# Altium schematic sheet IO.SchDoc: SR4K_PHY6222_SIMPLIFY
size A4; Revision: V1.2; SheetNumber: 5; SheetTotal: 5
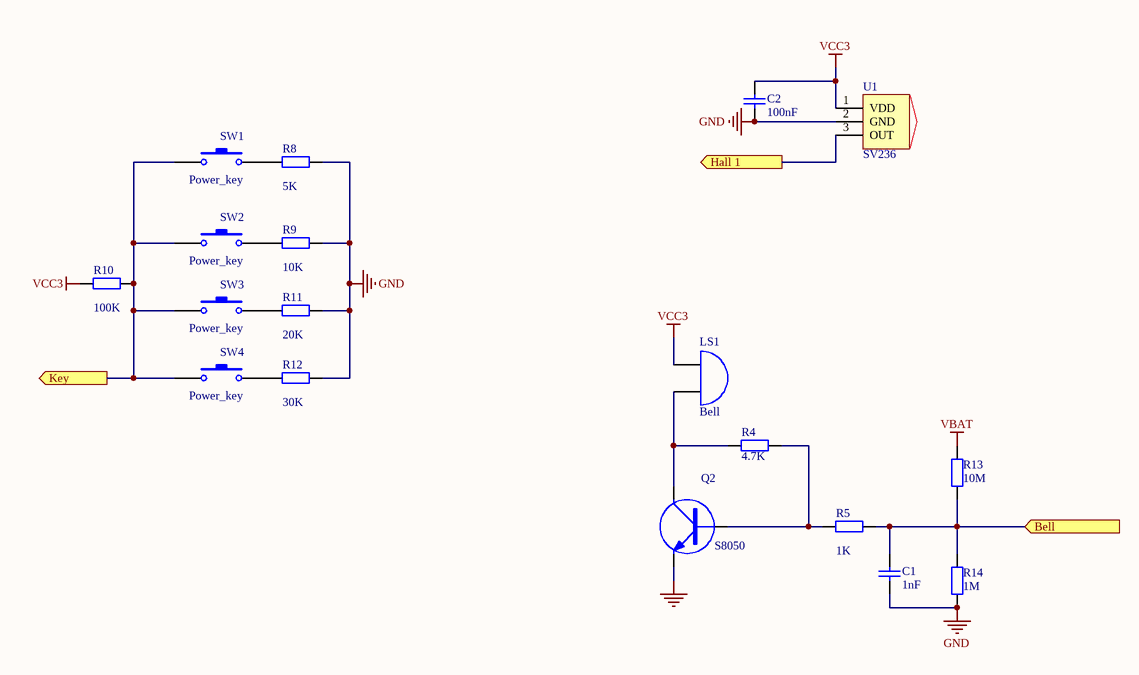
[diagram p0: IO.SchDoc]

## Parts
C1  value 1nF  [RAD-0.3]  (hidden comment: Cap)
C2  value 100nF  [RAD-0.3]  (hidden comment: Cap)
LS1  Bell
Q2  S8050  [SOT-23]
R4  value 4.7K  (hidden comment: 100K)
R5  value 1K  (hidden comment: Res2)
R8  value 5K  (hidden comment: Res2)
R9  value 10K  (hidden comment: Res2)
R10  value 100K  (hidden comment: Res2)
R11  value 20K  (hidden comment: Res2)
R12  value 30K  (hidden comment: Res2)
R13  value 10M  (hidden comment: Res2)
R14  value 1M  (hidden comment: Res2)
SW1  Power_key
SW2  Power_key
SW3  Power_key
SW4  Power_key
U1  SV236  [sot-23-3]

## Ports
Bell (in), Hall 1 (out), Key (out)

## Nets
GND: C1.2 C2.2 Q2.2(E) R8.2 R9.2 R11.2 R12.2 R14.1 U1.2(GND)
VBAT: R13.2
VCC3: C2.1 LS1.1(A) R10.1 U1.1(VDD)
Bell: C1.1 R5.2 R13.1 R14.2 ; port Bell
Hall 1: U1.3(OUT) ; port Hall 1
Key: R10.2 SW1.1 SW2.1 SW3.1 SW4.1 ; port Key
NetLS1_2: LS1.2(B) Q2.3(C) R4.2
NetQ2_1: Q2.1(B) R4.1 R5.1
NetR8_1: R8.1 SW1.2
NetR9_1: R9.1 SW2.2
NetR11_1: R11.1 SW3.2
NetR12_1: R12.1 SW4.2

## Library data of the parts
C1 C2 = Cap: Capacitor
LS1 = Bell: Electrical Bell
Q2 = NPN: NPN Transistor
R4 R5 R8-R14 = Res2: Resistor
SW1-SW4 = SW-PB: Switch
U1 = 霍尔44E 938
